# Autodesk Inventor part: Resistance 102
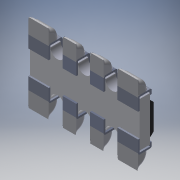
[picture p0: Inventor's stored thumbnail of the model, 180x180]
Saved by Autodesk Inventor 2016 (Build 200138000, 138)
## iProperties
Created: 2018-03
Part Number: Resistance 102
Material: Générique
Document SubType Name: Modeling
Designer: Bruno
Density: 1 g/cm^3
Appearance: Par défaut
Author: Bruno
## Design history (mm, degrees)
feature "Composite1"
body "Srf1"
